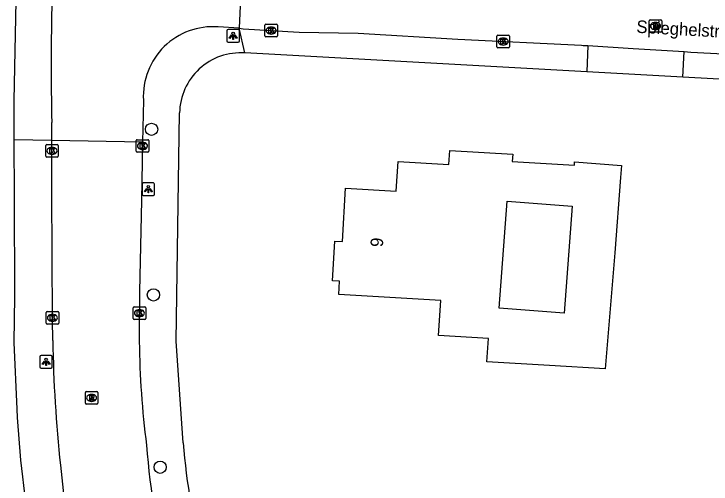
# Model space of a CAD drawing. Extents: x 161258 to 161838, y 380836 to 381727.
# Drawn here: x 161560.1 to 161615.9, y 381148.7 to 381186.3 of the extents above; entities that cross this region are included whole.
import ezdxf

# ---------------------------------------------------------------- set-up
doc = ezdxf.new("R2010")
doc.units = 0
for name, color, linetype in [('IMGEO_Boom', 7, 'Continuous'), ('IMGEO_Kolk', 7, 'Continuous'), ('IMGEO_Lichtpunt', 7, 'Continuous'), ('IMGEO_Openbare_ruimte_label', 7, 'Continuous'), ('IMGEO_Pand', 7, 'Continuous'), ('IMGEO_Pand_nummerreeks', 7, 'Continuous'), ('IMGEO_Rijbaan_lokaal_open', 7, 'Continuous'), ('IMGEO_Rioolput', 7, 'Continuous'), ('IMGEO_Voetpad_open', 7, 'Continuous')]:
    doc.layers.add(name, color=color, linetype=linetype)

msp = doc.modelspace()

# ---------------------------------------------------------------- linework, layer by layer
at = {"layer": 'IMGEO_Boom'}
for centre in [(161571.149, 381177.069), (161571.296, 381163.82), (161571.833, 381150.034)]:
    msp.add_circle(centre, 0.489, dxfattribs=at)
at = {"layer": 'IMGEO_Kolk'}
for p, q in [((161580.218, 381184.546), (161580.218, 381185.398)), ((161580.293, 381185.472), (161581.145, 381185.472)), ((161580.706, 381185.252), (161580.731, 381185.252)), ((161581.219, 381185.398), (161581.219, 381184.546)), ((161581.145, 381184.472), (161580.293, 381184.472)), ((161580.729, 381184.692), (161580.704, 381184.692)), ((161598.792, 381183.667), (161598.792, 381184.519)), ((161598.867, 381184.593), (161599.719, 381184.593)), ((161599.793, 381184.519), (161599.793, 381183.667)), ((161599.28, 381184.373), (161599.305, 381184.373)), ((161599.719, 381183.593), (161598.867, 381183.593)), ((161599.303, 381183.813), (161599.278, 381183.813)), ((161569.919, 381175.311), (161569.919, 381176.163)), ((161569.994, 381176.237), (161570.846, 381176.237)), ((161570.92, 381176.163), (161570.92, 381175.311)), ((161562.677, 381174.917), (161562.677, 381175.769)), ((161562.752, 381175.843), (161563.604, 381175.843)), ((161563.165, 381175.623), (161563.19, 381175.623)), ((161563.678, 381175.769), (161563.678, 381174.917)), ((161570.407, 381176.017), (161570.432, 381176.017)), ((161563.188, 381175.063), (161563.163, 381175.063)), ((161570.846, 381175.237), (161569.994, 381175.237)), ((161570.43, 381175.457), (161570.405, 381175.457)), ((161563.604, 381174.843), (161562.752, 381174.843)), ((161569.676, 381161.942), (161569.676, 381162.794)), ((161569.751, 381162.868), (161570.603, 381162.868)), ((161570.164, 381162.648), (161570.189, 381162.648)), ((161570.677, 381162.794), (161570.677, 381161.942)), ((161562.714, 381161.564), (161562.714, 381162.416)), ((161562.789, 381162.49), (161563.641, 381162.49)), ((161563.202, 381162.27), (161563.227, 381162.27)), ((161563.715, 381162.416), (161563.715, 381161.564)), ((161570.187, 381162.088), (161570.162, 381162.088)), ((161563.225, 381161.71), (161563.2, 381161.71)), ((161570.603, 381161.868), (161569.751, 381161.868)), ((161563.641, 381161.49), (161562.789, 381161.49))]:
    msp.add_line(p, q, dxfattribs=at)
for points in [[(161580.218, 381184.546), (161580.218, 381185.398)], [(161580.293, 381185.472), (161581.145, 381185.472)], [(161580.539, 381185.172), (161580.662, 381185.172), (161580.662, 381185.021), (161580.792, 381185.172), (161580.956, 381185.172), (161580.81, 381185.021), (161580.963, 381184.772), (161580.811, 381184.772), (161580.726, 381184.936), (161580.662, 381184.869), (161580.662, 381184.772), (161580.539, 381184.772), (161580.539, 381185.172)], [(161581.219, 381185.398), (161581.219, 381184.546)], [(161581.145, 381184.472), (161580.293, 381184.472)], [(161598.792, 381183.667), (161598.792, 381184.519)], [(161598.867, 381184.593), (161599.719, 381184.593)], [(161599.793, 381184.519), (161599.793, 381183.667)], [(161599.113, 381184.293), (161599.236, 381184.293), (161599.236, 381184.142), (161599.366, 381184.293), (161599.53, 381184.293), (161599.384, 381184.142), (161599.537, 381183.893), (161599.385, 381183.893), (161599.3, 381184.057), (161599.236, 381183.99), (161599.236, 381183.893), (161599.113, 381183.893), (161599.113, 381184.293)], [(161599.719, 381183.593), (161598.867, 381183.593)], [(161569.919, 381175.311), (161569.919, 381176.163)], [(161569.994, 381176.237), (161570.846, 381176.237)], [(161570.92, 381176.163), (161570.92, 381175.311)], [(161562.677, 381174.917), (161562.677, 381175.769)], [(161562.752, 381175.843), (161563.604, 381175.843)], [(161562.998, 381175.543), (161563.121, 381175.543), (161563.121, 381175.392), (161563.251, 381175.543), (161563.415, 381175.543), (161563.269, 381175.392), (161563.422, 381175.143), (161563.27, 381175.143), (161563.185, 381175.307), (161563.121, 381175.24), (161563.121, 381175.143), (161562.998, 381175.143), (161562.998, 381175.543)], [(161563.678, 381175.769), (161563.678, 381174.917)], [(161570.24, 381175.937), (161570.363, 381175.937), (161570.363, 381175.786), (161570.493, 381175.937), (161570.657, 381175.937), (161570.511, 381175.786), (161570.664, 381175.537), (161570.512, 381175.537), (161570.427, 381175.701), (161570.363, 381175.634), (161570.363, 381175.537), (161570.24, 381175.537), (161570.24, 381175.937)], [(161570.846, 381175.237), (161569.994, 381175.237)], [(161563.604, 381174.843), (161562.752, 381174.843)], [(161569.676, 381161.942), (161569.676, 381162.794)], [(161569.751, 381162.868), (161570.603, 381162.868)], [(161570.677, 381162.794), (161570.677, 381161.942)], [(161562.714, 381161.564), (161562.714, 381162.416)], [(161562.789, 381162.49), (161563.641, 381162.49)], [(161563.035, 381162.19), (161563.158, 381162.19), (161563.158, 381162.039), (161563.288, 381162.19), (161563.452, 381162.19), (161563.306, 381162.039), (161563.459, 381161.79), (161563.307, 381161.79), (161563.222, 381161.954), (161563.158, 381161.887), (161563.158, 381161.79), (161563.035, 381161.79), (161563.035, 381162.19)], [(161563.715, 381162.416), (161563.715, 381161.564)], [(161569.997, 381162.568), (161570.12, 381162.568), (161570.12, 381162.417), (161570.25, 381162.568), (161570.414, 381162.568), (161570.268, 381162.417), (161570.421, 381162.168), (161570.269, 381162.168), (161570.184, 381162.332), (161570.12, 381162.265), (161570.12, 381162.168), (161569.997, 381162.168), (161569.997, 381162.568)], [(161570.603, 381161.868), (161569.751, 381161.868)], [(161563.641, 381161.49), (161562.789, 381161.49)]]:
    msp.add_lwpolyline(points, dxfattribs=at)
for centre, start, end in [((161580.295, 381185.396), 91.552, 178.448), ((161580.295, 381185.396), 91.552, 178.448), ((161581.143, 381185.396), 1.552, 88.448), ((161581.143, 381185.396), 1.552, 88.448), ((161580.295, 381184.548), 181.552, 268.448), ((161580.295, 381184.548), 181.552, 268.448), ((161581.143, 381184.548), 271.552, 358.448), ((161581.143, 381184.548), 271.552, 358.448), ((161598.869, 381184.517), 91.552, 178.448), ((161598.869, 381184.517), 91.552, 178.448), ((161599.717, 381184.517), 1.552, 88.448), ((161599.717, 381184.517), 1.552, 88.448), ((161598.869, 381183.669), 181.552, 268.448), ((161598.869, 381183.669), 181.552, 268.448), ((161599.717, 381183.669), 271.552, 358.448), ((161599.717, 381183.669), 271.552, 358.448), ((161569.996, 381176.161), 91.552, 178.448), ((161569.996, 381176.161), 91.552, 178.448), ((161570.844, 381176.161), 1.552, 88.448), ((161570.844, 381176.161), 1.552, 88.448), ((161562.754, 381175.767), 91.552, 178.448), ((161562.754, 381175.767), 91.552, 178.448), ((161563.602, 381175.767), 1.552, 88.448), ((161563.602, 381175.767), 1.552, 88.448), ((161562.754, 381174.919), 181.552, 268.448), ((161562.754, 381174.919), 181.552, 268.448), ((161563.602, 381174.919), 271.552, 358.448), ((161563.602, 381174.919), 271.552, 358.448), ((161569.996, 381175.313), 181.552, 268.448), ((161569.996, 381175.313), 181.552, 268.448), ((161570.844, 381175.313), 271.552, 358.448), ((161570.844, 381175.313), 271.552, 358.448), ((161569.753, 381162.792), 91.552, 178.448), ((161569.753, 381162.792), 91.552, 178.448), ((161570.601, 381162.792), 1.552, 88.448), ((161570.601, 381162.792), 1.552, 88.448), ((161562.791, 381162.414), 91.552, 178.448), ((161562.791, 381162.414), 91.552, 178.448), ((161563.639, 381162.414), 1.552, 88.448), ((161563.639, 381162.414), 1.552, 88.448), ((161562.791, 381161.566), 181.552, 268.448), ((161562.791, 381161.566), 181.552, 268.448), ((161563.639, 381161.566), 271.552, 358.448), ((161563.639, 381161.566), 271.552, 358.448), ((161569.753, 381161.944), 181.552, 268.448), ((161569.753, 381161.944), 181.552, 268.448), ((161570.601, 381161.944), 271.552, 358.448), ((161570.601, 381161.944), 271.552, 358.448)]:
    msp.add_arc(centre, 0.0765, start, end, dxfattribs=at)
for centre, major_axis, ratio, start_param, end_param in [((161580.705, 381184.972), (-0.387, 0.002), 0.722429, 4.712389, 7.853982), ((161580.73, 381184.972), (-0.39, 0.002), 0.717154, 1.570796, 4.712389), ((161599.279, 381184.093), (-0.387, 0.002), 0.722429, 4.712389, 7.853982), ((161599.304, 381184.093), (-0.39, 0.002), 0.717154, 1.570796, 4.712389), ((161570.406, 381175.737), (-0.387, 0.002), 0.722429, 4.712389, 7.853982), ((161563.164, 381175.343), (-0.387, 0.002), 0.722429, 4.712389, 7.853982), ((161563.189, 381175.343), (-0.39, 0.002), 0.717154, 1.570796, 4.712389), ((161570.431, 381175.737), (-0.39, 0.002), 0.717154, 1.570796, 4.712389), ((161570.163, 381162.368), (-0.387, 0.002), 0.722429, 4.712389, 7.853982), ((161570.188, 381162.368), (-0.39, 0.002), 0.717154, 1.570796, 4.712389), ((161563.201, 381161.99), (-0.387, 0.002), 0.722429, 4.712389, 7.853982), ((161563.226, 381161.99), (-0.39, 0.002), 0.717154, 1.570796, 4.712389)]:
    msp.add_ellipse(centre, major_axis=major_axis, ratio=ratio, start_param=start_param, end_param=end_param, dxfattribs=at)
at = {"layer": 'IMGEO_Lichtpunt'}
for p, q in [((161577.181, 381184.952), (161577.181, 381184.145)), ((161577.181, 381184.952), (161577.181, 381184.145)), ((161578.083, 381185.047), (161577.275, 381185.047)), ((161578.083, 381185.047), (161577.275, 381185.047)), ((161578.177, 381184.145), (161578.177, 381184.952)), ((161578.177, 381184.145), (161578.177, 381184.952)), ((161577.275, 381184.051), (161578.083, 381184.051)), ((161577.275, 381184.051), (161578.083, 381184.051)), ((161570.387, 381172.681), (161570.387, 381171.874)), ((161570.387, 381172.681), (161570.387, 381171.874)), ((161571.289, 381172.776), (161570.481, 381172.776)), ((161571.289, 381172.776), (161570.481, 381172.776)), ((161571.383, 381171.874), (161571.383, 381172.681)), ((161571.383, 381171.874), (161571.383, 381172.681)), ((161570.481, 381171.78), (161571.289, 381171.78)), ((161570.481, 381171.78), (161571.289, 381171.78)), ((161562.207, 381158.871), (161562.207, 381158.064)), ((161562.207, 381158.871), (161562.207, 381158.064)), ((161563.109, 381158.966), (161562.301, 381158.966)), ((161563.109, 381158.966), (161562.301, 381158.966)), ((161563.203, 381158.064), (161563.203, 381158.871)), ((161563.203, 381158.064), (161563.203, 381158.871)), ((161562.301, 381157.97), (161563.109, 381157.97)), ((161562.301, 381157.97), (161563.109, 381157.97))]:
    msp.add_line(p, q, dxfattribs=at)
for points in [[(161577.555, 381184.616), (161577.594, 381184.588), (161577.406, 381184.326), (161577.368, 381184.353), (161577.555, 381184.616)], [(161577.657, 381184.568), (161577.704, 381184.568), (161577.704, 381184.246), (161577.657, 381184.246), (161577.657, 381184.568)], [(161577.767, 381184.588), (161577.805, 381184.615), (161577.992, 381184.353), (161577.953, 381184.325), (161577.767, 381184.588)], [(161570.761, 381172.345), (161570.8, 381172.317), (161570.612, 381172.055), (161570.574, 381172.082), (161570.761, 381172.345)], [(161570.863, 381172.297), (161570.91, 381172.297), (161570.91, 381171.975), (161570.863, 381171.975), (161570.863, 381172.297)], [(161570.973, 381172.317), (161571.011, 381172.344), (161571.198, 381172.082), (161571.159, 381172.054), (161570.973, 381172.317)], [(161562.581, 381158.535), (161562.62, 381158.507), (161562.432, 381158.245), (161562.394, 381158.272), (161562.581, 381158.535)], [(161562.683, 381158.487), (161562.73, 381158.487), (161562.73, 381158.165), (161562.683, 381158.165), (161562.683, 381158.487)], [(161562.793, 381158.507), (161562.831, 381158.534), (161563.018, 381158.272), (161562.979, 381158.244), (161562.793, 381158.507)]]:
    msp.add_lwpolyline(points, dxfattribs=at)
for centre in [(161577.68, 381184.75), (161570.886, 381172.479), (161562.706, 381158.669)]:
    msp.add_circle(centre, 0.0994, dxfattribs=at)
for centre, start, end in [((161577.275, 381184.952), 90, 180), ((161577.275, 381184.952), 90, 180), ((161578.083, 381184.952), 0, 90), ((161578.083, 381184.952), 0, 90), ((161577.275, 381184.145), 180, 270), ((161577.275, 381184.145), 180, 270), ((161578.083, 381184.145), 270, 0), ((161578.083, 381184.145), 270, 360), ((161570.481, 381172.681), 90, 180), ((161570.481, 381172.681), 90, 180), ((161571.289, 381172.681), 0, 90), ((161571.289, 381172.681), 0, 90), ((161570.481, 381171.874), 180, 270), ((161570.481, 381171.874), 180, 270), ((161571.289, 381171.874), 270, 0), ((161571.289, 381171.874), 270, 360), ((161562.301, 381158.871), 90, 180), ((161562.301, 381158.871), 90, 180), ((161563.109, 381158.871), 0, 90), ((161563.109, 381158.871), 0, 90), ((161562.301, 381158.064), 180, 270), ((161562.301, 381158.064), 180, 270), ((161563.109, 381158.064), 270, 0), ((161563.109, 381158.064), 270, 360)]:
    msp.add_arc(centre, 0.0946, start, end, dxfattribs=at)
at = {"layer": 'IMGEO_Pand'}
for points in [[(161597.996, 381158.475), (161598.105, 381160.34), (161594.127, 381160.573), (161594.291, 381163.383), (161586.126, 381163.861), (161586.187, 381164.909), (161585.627, 381164.942), (161585.813, 381168.122), (161586.429, 381168.086), (161586.681, 381172.371), (161590.739, 381172.133), (161590.877, 381174.493), (161594.944, 381174.254), (161595.009, 381175.37), (161600.054, 381175.074), (161600.02, 381174.494), (161604.99, 381174.203), (161604.995, 381174.476), (161608.77, 381174.186), (161608.696, 381173.215), (161608.237, 381167.197), (161607.464, 381157.921), (161602.988, 381158.183), (161597.996, 381158.475)], [(161604.161, 381162.37), (161598.961, 381162.763), (161599.608, 381171.315), (161604.808, 381170.922), (161604.161, 381162.37)]]:
    msp.add_lwpolyline(points, dxfattribs=at)
at = {"layer": 'IMGEO_Rijbaan_lokaal_open'}
for points in [[(161578.352, 381189.346), (161578.149, 381185.166)], [(161578.149, 381185.166), (161576.474, 381185.258)], [(161578.149, 381185.166), (161578.476, 381185.106), (161582.962, 381184.838), (161587.685, 381184.756), (161595.649, 381184.269), (161605.573, 381183.794), (161605.683, 381183.787), (161606.069, 381183.763)], [(161606.069, 381183.763), (161609.697, 381183.539), (161613.779, 381183.287)], [(161613.779, 381183.287), (161614.308, 381183.254), (161619.552, 381182.967)], [(161570.493, 381179.405), (161570.424, 381176.029)], [(161563.163, 381176.176), (161563.158, 381177.603)], [(161563.238, 381160.182), (161563.216, 381161.851), (161563.177, 381172.104), (161563.163, 381176.176)], [(161570.424, 381176.029), (161563.163, 381176.176)], [(161570.424, 381176.029), (161570.33, 381171.378), (161570.184, 381164.098), (161570.165, 381160.091)]]:
    msp.add_lwpolyline(points, dxfattribs=at)
for centre, radius, start, end in [((161798.498, 381182.228), 235.386, 176.34245, 181.12587), ((161576.046, 381179.713), 5.561, 85.5814, 183.1792), ((161676.281, 381162.109), 113.06, 180.97683, 186.04866), ((161639.35, 381160.777), 69.188, 180.56774, 187.45217), ((161626.272, 381155.862), 55.674, 184.1805, 195.6201), ((161635.907, 381156.982), 72.375, 185.37995, 198.2305)]:
    msp.add_arc(centre, radius, start, end, dxfattribs=at)
at = {"layer": 'IMGEO_Rioolput'}
for p, q in [((161610.985, 381184.908), (161610.985, 381185.76)), ((161611.06, 381185.834), (161611.912, 381185.834)), ((161611.473, 381185.614), (161611.498, 381185.614)), ((161611.986, 381185.76), (161611.986, 381184.908)), ((161611.496, 381185.054), (161611.471, 381185.054)), ((161611.912, 381184.834), (161611.06, 381184.834)), ((161565.848, 381155.162), (161565.848, 381156.014)), ((161565.923, 381156.088), (161566.775, 381156.088)), ((161566.849, 381156.014), (161566.849, 381155.162)), ((161566.336, 381155.868), (161566.361, 381155.868)), ((161566.775, 381155.088), (161565.923, 381155.088)), ((161566.359, 381155.308), (161566.334, 381155.308))]:
    msp.add_line(p, q, dxfattribs=at)
for points in [[(161610.985, 381184.908), (161610.985, 381185.76)], [(161611.06, 381185.834), (161611.912, 381185.834)], [(161611.574, 381185.532), (161611.322, 381185.534), (161611.322, 381185.134)], [(161611.986, 381185.76), (161611.986, 381184.908)], [(161611.322, 381185.134), (161611.446, 381185.134), (161611.446, 381185.296), (161611.457, 381185.296)], [(161611.5, 381185.453), (161611.446, 381185.453), (161611.446, 381185.372)], [(161611.446, 381185.372), (161611.498, 381185.372)], [(161611.504, 381185.267), (161611.575, 381185.134), (161611.715, 381185.134), (161611.65, 381185.26)], [(161611.912, 381184.834), (161611.06, 381184.834)], [(161565.848, 381155.162), (161565.848, 381156.014)], [(161565.923, 381156.088), (161566.775, 381156.088)], [(161566.849, 381156.014), (161566.849, 381155.162)], [(161566.437, 381155.786), (161566.185, 381155.788), (161566.185, 381155.388)], [(161566.185, 381155.388), (161566.309, 381155.388), (161566.309, 381155.55), (161566.32, 381155.55)], [(161566.363, 381155.707), (161566.309, 381155.707), (161566.309, 381155.626)], [(161566.309, 381155.626), (161566.361, 381155.626)], [(161566.367, 381155.521), (161566.438, 381155.388), (161566.578, 381155.388), (161566.513, 381155.514)], [(161566.775, 381155.088), (161565.923, 381155.088)]]:
    msp.add_lwpolyline(points, dxfattribs=at)
for centre, radius, start, end in [((161611.062, 381185.758), 0.0765, 91.552, 178.448), ((161611.062, 381185.758), 0.0765, 91.552, 178.448), ((161611.573, 381185.422), 0.109, 350.3612, 89.416), ((161611.91, 381185.758), 0.0765, 1.552, 88.448), ((161611.91, 381185.758), 0.0765, 1.552, 88.448), ((161611.456, 381185.243), 0.0533, 26.0293, 88.6989), ((161611.482, 381185.561), 0.19, 274.7715, 282.9687), ((161611.506, 381185.357), 0.0964, 77.0061, 93.1865), ((161611.52, 381185.414), 0.0378, 276.6634, 79.6772), ((161611.571, 381185.422), 0.112, 277.5842, 350.9817), ((161611.555, 381185.207), 0.108, 29.5134, 73.7905), ((161611.062, 381184.91), 0.0765, 181.552, 268.448), ((161611.062, 381184.91), 0.0765, 181.552, 268.448), ((161611.91, 381184.91), 0.0765, 271.552, 358.448), ((161611.91, 381184.91), 0.0765, 271.552, 358.448), ((161565.925, 381156.012), 0.0765, 91.552, 178.448), ((161565.925, 381156.012), 0.0765, 91.552, 178.448), ((161566.773, 381156.012), 0.0765, 1.552, 88.448), ((161566.773, 381156.012), 0.0765, 1.552, 88.448), ((161566.319, 381155.497), 0.0533, 26.0293, 88.6989), ((161566.345, 381155.815), 0.19, 274.7715, 282.9687), ((161566.369, 381155.611), 0.0964, 77.0061, 93.1865), ((161566.383, 381155.668), 0.0378, 276.6634, 79.6772), ((161566.436, 381155.676), 0.109, 350.3612, 89.416), ((161566.434, 381155.676), 0.112, 277.5842, 350.9817), ((161566.418, 381155.461), 0.108, 29.5134, 73.7905), ((161565.925, 381155.164), 0.0765, 181.552, 268.448), ((161565.925, 381155.164), 0.0765, 181.552, 268.448), ((161566.773, 381155.164), 0.0765, 271.552, 358.448), ((161566.773, 381155.164), 0.0765, 271.552, 358.448)]:
    msp.add_arc(centre, radius, start, end, dxfattribs=at)
for centre, major_axis, ratio, start_param, end_param in [((161611.472, 381185.334), (-0.387, 0.002), 0.722429, 4.712389, 7.853982), ((161611.497, 381185.334), (-0.39, 0.002), 0.717154, 1.570796, 4.712389), ((161566.335, 381155.588), (-0.387, 0.002), 0.722429, 4.712389, 7.853982), ((161566.36, 381155.588), (-0.39, 0.002), 0.717154, 1.570796, 4.712389)]:
    msp.add_ellipse(centre, major_axis=major_axis, ratio=ratio, start_param=start_param, end_param=end_param, dxfattribs=at)
at = {"layer": 'IMGEO_Voetpad_open'}
for points in [[(161561.183, 381212.553), (161560.87, 381203.99), (161560.54, 381195.569), (161560.289, 381187.309), (161560.131, 381179.362), (161560.133, 381176.238)], [(161578.621, 381183.178), (161578.149, 381185.166)], [(161606.069, 381183.763), (161605.999, 381181.658)], [(161613.67, 381181.233), (161613.779, 381183.287)], [(161605.999, 381181.658), (161605.515, 381181.685), (161578.621, 381183.178)], [(161613.67, 381181.233), (161609.363, 381181.472), (161605.999, 381181.658)], [(161619.983, 381180.882), (161613.67, 381181.233)], [(161573.665, 381151.99), (161573.114, 381160.117), (161573.39, 381178.375)], [(161563.163, 381176.176), (161560.133, 381176.238)], [(161560.133, 381176.238), (161560.137, 381171.653), (161560.174, 381163.7), (161560.133, 381160.014), (161560.363, 381154.689)]]:
    msp.add_lwpolyline(points, dxfattribs=at)
for centre, radius, start, end in [((161578.27, 381178.31), 4.88, 85.8743, 179.2408), ((161640.454, 381158.52), 80.183, 182.73851, 198.30765), ((161631.533, 381156.99), 58.084, 184.93837, 194.58058)]:
    msp.add_arc(centre, radius, start, end, dxfattribs=at)

# ---------------------------------------------------------------- texts
at = {"layer": 'IMGEO_Openbare_ruimte_label'}
msp.add_text('Spieghelstraat', height=1, rotation=356.7311, dxfattribs=at).set_placement((161609.932, 381184.797))
at = {"layer": 'IMGEO_Pand_nummerreeks'}
msp.add_text('9', height=1, rotation=86.2686, dxfattribs=at).set_placement((161589.658, 381167.627))

doc.saveas('drawing.dxf')
